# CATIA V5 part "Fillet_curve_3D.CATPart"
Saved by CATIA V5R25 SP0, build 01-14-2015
Part number: Part1
Bounding box of the stored display mesh (mm): x -53.144 to 62.813, y -26.849 to 28.605, z -46.959 to 56.805
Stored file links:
  E:\cadcim\GSD_cat_v5-6r2014\Part_files\Fillet_curve_3D.CATPart
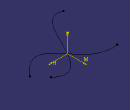
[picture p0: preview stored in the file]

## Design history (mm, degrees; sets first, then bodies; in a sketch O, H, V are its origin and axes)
Body1 (main body)
  Sketch1 on xy-plane, origin (0, 0, 0), H (1, 0, 0), V (0, 1, 0)
    spline S1 through (-53.144, 27.9693) (-18.6897, 19.5729) (20.5127, -19.6499) (62.8125, 1.293)
    coincidence: O S1
  Sketch2 on yz-plane, origin (0, 0, 0), H (0, 1, 0), V (0, 0, 1)
    spline S1 through (-6.7941, 56.8054) (-23.6522, 28.3211) (0, 0) (-26.8494, -46.959)
    point P1 (0, 0)
    coincidence: P1 H, P1 O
